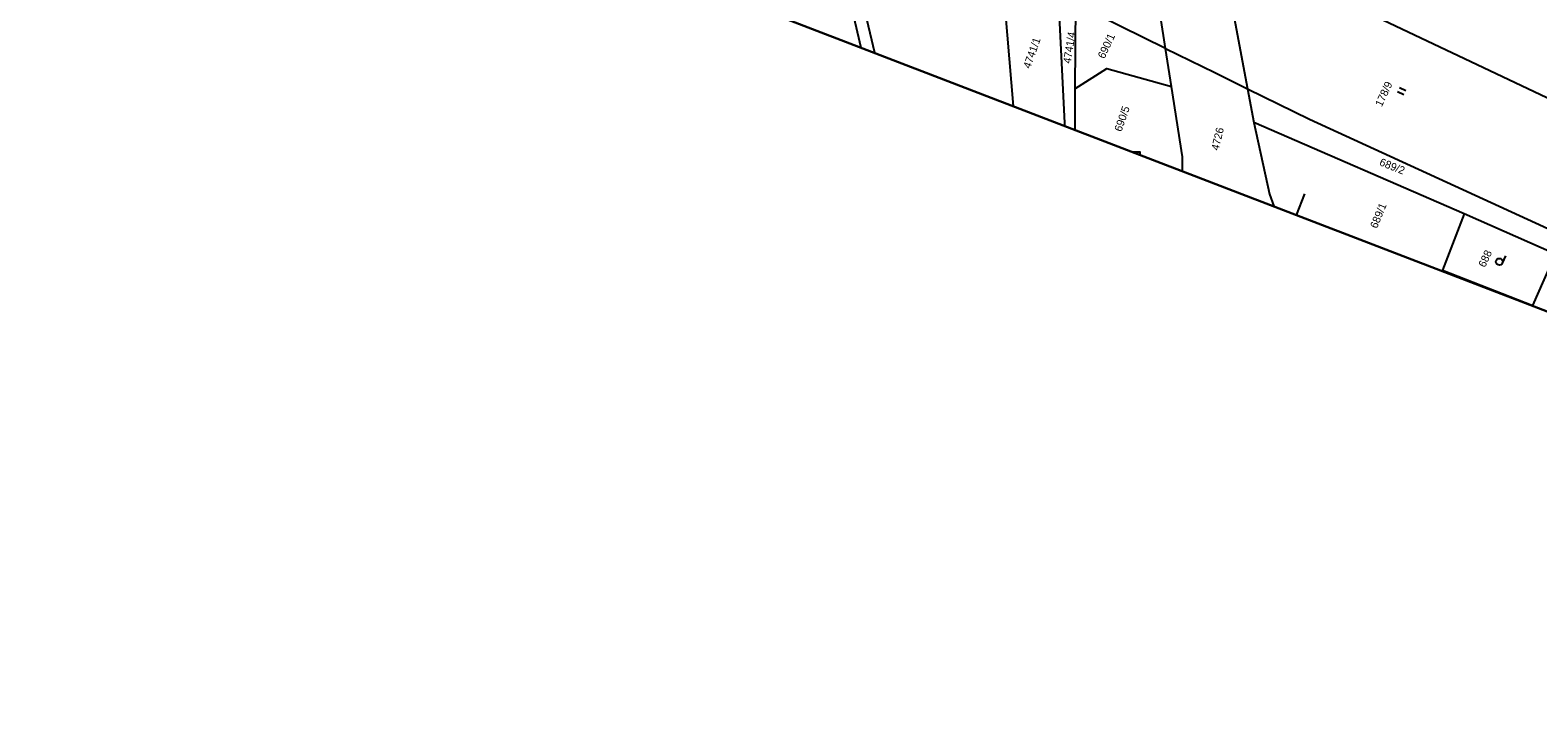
# Model space of a CAD drawing. Extents: x -755344 to -754412, y -1162670 to -1161477.
# Drawn here: x -755344.1 to -755014.1, y -1162670.3 to -1162523.1 of the extents above; entities that cross this region are included whole.
import ezdxf

# ---------------------------------------------------------------- set-up
doc = ezdxf.new("R2010")
doc.units = 0
for name, color, linetype in [('Formát', 7, 'Continuous'), ('Katastrální hranice', 7, 'Continuous'), ('Vrstva 55', 7, 'Continuous'), ('Vrstva 57', 7, 'Continuous'), ('Vrstva 58', 7, 'Continuous')]:
    doc.layers.add(name, color=color, linetype=linetype)

msp = doc.modelspace()

# ---------------------------------------------------------------- linework, layer by layer
at = {"layer": 'Formát'}
for p, q in [((-755344.08, -1162456.97), (-754789.71, -1162670.32)), ((-755066.89, -1162563.65), (-755065.1, -1162558.98))]:
    msp.add_line(p, q, dxfattribs=at)
msp.add_lwpolyline([(-754488.01, -1161886.37), (-754789.71, -1162670.32), (-755344.08, -1162456.97), (-755042.37, -1161673.02)], close=True, dxfattribs=at)
msp.add_lwpolyline([(-755344.08, -1162456.97), (-754789.71, -1162670.32), (-754488.01, -1161886.37), (-755042.37, -1161673.02)], dxfattribs=at)
msp.add_lwpolyline([(-755344.08, -1162456.97), (-754789.71, -1162670.32), (-754488.01, -1161886.37), (-755042.37, -1161673.02)], dxfattribs=at)
at = {"layer": 'Katastrální hranice'}
msp.add_line((-755064.06, -1162542.65), (-755010.16, -1162567.43), dxfattribs=at)
at = {"layer": 'Vrstva 55'}
for p, q in [((-755169.63, -1162495.32), (-755162.24, -1162526.95)), ((-754997.93, -1162544.71), (-755083.94, -1162503.85)), ((-755115.23, -1162517.45), (-755115.39, -1162536.04)), ((-755095.54, -1162527.15), (-755115.23, -1162517.45)), ((-755095.54, -1162527.15), (-755115.23, -1162517.45)), ((-755094.23, -1162535.53), (-755095.54, -1162527.15)), ((-755077.64, -1162535.97), (-755064.06, -1162542.65)), ((-755077.64, -1162535.97), (-755064.06, -1162542.65)), ((-755077.64, -1162535.97), (-755076.22, -1162543.36)), ((-755030.16, -1162563.38), (-755076.22, -1162543.36)), ((-755076.22, -1162543.36), (-755072.83, -1162559.11)), ((-755064.06, -1162542.65), (-755010.16, -1162567.43)), ((-755064.06, -1162542.65), (-755010.16, -1162567.43)), ((-755030.16, -1162563.38), (-755034.91, -1162575.76)), ((-755010.18, -1162572.23), (-755030.16, -1162563.38)), ((-755034.98, -1162575.93), (-755034.91, -1162575.76))]:
    msp.add_line(p, q, dxfattribs=at)
for points in [[(-755128.8, -1162539.82), (-755131.98, -1162502.55), (-755133.78, -1162491.69)], [(-755159.22, -1162528.11), (-755167.04, -1162494.84)], [(-755095.54, -1162527.15), (-755098.96, -1162504.9), (-755101.11, -1162495.7)], [(-755083.94, -1162503.85), (-755082.47, -1162509.84), (-755077.64, -1162535.97)], [(-755117.62, -1162544.13), (-755117.62, -1162543.52), (-755118.95, -1162515.63)], [(-755095.54, -1162527.15), (-755084.75, -1162532.46), (-755077.64, -1162535.97)], [(-755095.54, -1162527.15), (-755084.75, -1162532.46), (-755077.64, -1162535.97)], [(-755115.39, -1162536.04), (-755108.39, -1162531.55), (-755094.23, -1162535.53)], [(-755115.39, -1162536.04), (-755115.42, -1162544.97)], [(-755091.81, -1162554.06), (-755091.84, -1162550.88), (-755094.23, -1162535.53)], [(-755101.14, -1162550.47), (-755101.14, -1162549.87), (-755102.7, -1162549.87)], [(-755072.83, -1162559.11), (-755071.86, -1162561.73)], [(-755034.91, -1162575.76), (-755015.17, -1162583.46), (-755010.18, -1162572.23)]]:
    msp.add_lwpolyline(points, dxfattribs=at)
at = {"layer": 'Vrstva 58'}
for p, q in [((-755043.41, -1162537.31), (-755044.77, -1162536.68)), ((-755042.98, -1162536.41), (-755044.34, -1162535.77)), ((-755021.81, -1162574.22), (-755021.07, -1162572.63))]:
    msp.add_line(p, q, dxfattribs=at)
msp.add_circle((-755022.49, -1162573.9), 0.75, dxfattribs=at)

# ---------------------------------------------------------------- texts
at = {"layer": 'Vrstva 57'}
for s, rotation, p in [('4741/4', 81, (-755116.32, -1162530.55)), ('4741/1', 70.5734, (-755125.18, -1162531.7)), ('690/1', 65, (-755108.94, -1162529.54)), ('178/9', 65, (-755048.23, -1162540.07)), ('690/5', 70.8343, (-755105.22, -1162545.52)), ('4726', 76.4903, (-755083.94, -1162549.62)), ('689/2', 338.336, (-755048.89, -1162552.71)), ('689/1', 67.7974, (-755049.28, -1162566.73)), ('688', 65, (-755025.63, -1162575.27))]:
    msp.add_text(s, height=1.7, rotation=rotation, dxfattribs=at).set_placement(p)

doc.saveas('drawing.dxf')
